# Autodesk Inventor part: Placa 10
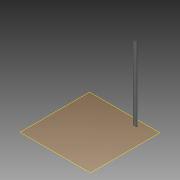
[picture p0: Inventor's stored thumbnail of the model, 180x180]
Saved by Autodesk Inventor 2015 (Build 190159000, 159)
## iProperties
Created: 2015-04
Part Number: Placa 10
Material: Generic
Document SubType Name: Modeling
Designer: suporte
Density: 1 g/cm^3
Appearance: Default
Author: suporte
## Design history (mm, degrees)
workplane "Work Plane1"
sketch "Sketch1"
  geometry: L1 (530.862, 800)-(530.862, 898.918) reference; L2 (430.862, 812.5)-(430.862, 800) reference; L3 (430.862, 812.5)-(530.862, 812.5); L4 (530.862, 812.5)-(530.862, 800); L5 (530.862, 800)-(430.862, 800); L6 (430.862, 800)-(430.862, 812.5); 1 further point
  constraints: 8 end point, 2 parallel, 1 horizontal, 1 perpendicular
extrude "Extrusion1" new body sketch "Sketch1" distance "d0" = 2100; taper "d1" = 0 deg
body "Solid1"
node "Reference1"
node "Reference2"
